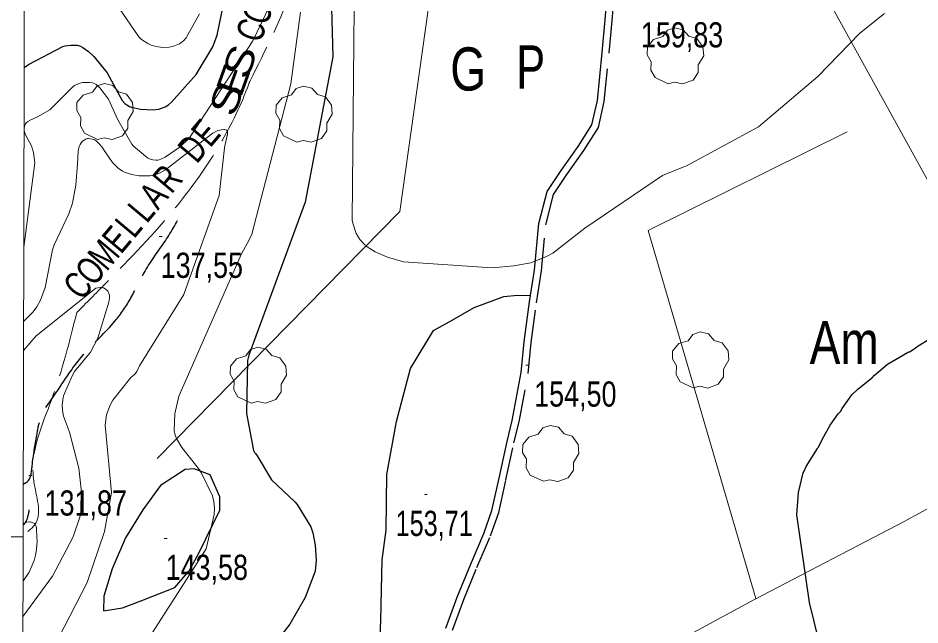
# Model space of a CAD drawing. Extents: x 483847 to 488453, y 4383581 to 4386795.
# Drawn here: x 484099.5 to 484413.1, y 4384469.3 to 4384680.3 of the extents above; entities that cross this region are included whole.
import ezdxf
from ezdxf.enums import TextEntityAlignment as Align

# ---------------------------------------------------------------- set-up
doc = ezdxf.new("R2010")
doc.units = 0
doc.header["$LTSCALE"] = 3.8
doc.linetypes.add('LONG_DASHED', pattern=[7.5, 6, -1.5])
doc.linetypes.add('MEDIUM_DASHED', pattern=[4.5, 3, -1.5])
for name, color, linetype, lineweight in [('1', 7, 'Continuous', 13), ('15', 7, 'LONG_DASHED', 13), ('25', 7, 'LONG_DASHED', 25), ('29', 7, 'Continuous', 13), ('38', 7, 'Continuous', 25), ('51', 7, 'Continuous', 13), ('7', 7, 'Continuous', 13), ('8', 7, 'Continuous', 25), ('9', 7, 'Continuous', 13)]:
    doc.layers.add(name, color=color, linetype=linetype, lineweight=lineweight)
doc.layers.add('31', color=7, linetype='Continuous')
doc.layers.add('5', color=7, linetype='Continuous')

msp = doc.modelspace()

# ---------------------------------------------------------------- linework, layer by layer
at = {"layer": '1'}
msp.add_line((484101.29, 4384500), (484031.19, 4384500), dxfattribs=at)
msp.add_lwpolyline([(484105.5, 4386448.1), (487681.9, 4386441.2), (487678, 4384129), (484100.5, 4384135.8)], close=True, dxfattribs=at)
at = {"layer": '15'}
for points in [[(484208.62, 4384780.98), (484204.46, 4384734.17), (484194.95, 4384691.19), (484180.05, 4384658.27)], [(484180.05, 4384658.27), (484179.75, 4384657.45), (484169.76, 4384636.54), (484154.56, 4384614.85), (484129.82, 4384587.96), (484119.88, 4384577.91)], [(484119.88, 4384577.91), (484111.2, 4384547.84), (484104.97, 4384519.31), (484105.58, 4384504.64), (484101.29, 4384500.6)]]:
    msp.add_spline(points, degree=3, dxfattribs=at)
at = {"layer": '25'}
msp.add_lwpolyline([(484247.62, 4384429.46), (484230.21, 4384421.96), (484225.82, 4384423.25), (484225.2, 4384427.09), (484224.83, 4384448.41), (484225.68, 4384470.98), (484226.15, 4384492), (484227.55, 4384502.3), (484227.75, 4384521.67), (484231.1, 4384540.04), (484235.95, 4384558.53), (484243.96, 4384571.74), (484250.5, 4384575.32), (484258.08, 4384579.74), (484268.39, 4384583.53), (484273.18, 4384583.98), (484277.7, 4384583.83)], dxfattribs=at)
msp.add_lwpolyline([(484162.32, 4384494.35), (484169.61, 4384509.2), (484169.64, 4384513.86), (484166.33, 4384521.56), (484160.73, 4384523.57), (484157.57, 4384523.34), (484149.04, 4384517.85), (484142.87, 4384509.33), (484136.8, 4384499.68), (484132.17, 4384488.8), (484129.27, 4384479.31), (484129.23, 4384474.25), (484135.76, 4384475.29), (484142.56, 4384477.86), (484154.01, 4384482.35), (484158.99, 4384488.17)], close=True, dxfattribs=at)
at = {"layer": '29'}
for points in [[(484325.53, 4384657.49), (484320.99, 4384659.61), (484319.58, 4384662.15), (484319.68, 4384665.13), (484318.31, 4384667.54), (484318.35, 4384670.29), (484320.51, 4384672.89), (484323.7, 4384673.89), (484325.35, 4384676.08), (484327.92, 4384676.91), (484330.78, 4384676.26), (484332.73, 4384673.99), (484335.54, 4384673.17), (484337.67, 4384670.32), (484337.91, 4384667.19), (484336.03, 4384664.04), (484336.03, 4384661.36), (484334.21, 4384658.75), (484330.59, 4384657.41), (484327.82, 4384658.04)], [(484127.16, 4384638.16), (484122.62, 4384640.28), (484121.21, 4384642.82), (484121.31, 4384645.8), (484119.94, 4384648.21), (484119.98, 4384650.96), (484122.14, 4384653.56), (484125.33, 4384654.56), (484126.98, 4384656.75), (484129.55, 4384657.58), (484132.41, 4384656.93), (484134.36, 4384654.66), (484137.17, 4384653.84), (484139.3, 4384650.99), (484139.54, 4384647.86), (484137.66, 4384644.71), (484137.66, 4384642.03), (484135.84, 4384639.42), (484132.22, 4384638.08), (484129.45, 4384638.71)], [(484196.38, 4384637.21), (484191.84, 4384639.33), (484190.43, 4384641.87), (484190.53, 4384644.85), (484189.16, 4384647.26), (484189.2, 4384650.01), (484191.36, 4384652.61), (484194.55, 4384653.61), (484196.2, 4384655.8), (484198.77, 4384656.63), (484201.63, 4384655.98), (484203.58, 4384653.71), (484206.39, 4384652.89), (484208.52, 4384650.04), (484208.76, 4384646.91), (484206.88, 4384643.76), (484206.88, 4384641.08), (484205.06, 4384638.47), (484201.44, 4384637.13), (484198.67, 4384637.76)], [(484334.3, 4384551.77), (484329.76, 4384553.89), (484328.35, 4384556.43), (484328.45, 4384559.41), (484327.08, 4384561.82), (484327.12, 4384564.57), (484329.28, 4384567.17), (484332.47, 4384568.17), (484334.12, 4384570.36), (484336.69, 4384571.19), (484339.55, 4384570.54), (484341.5, 4384568.27), (484344.31, 4384567.45), (484346.44, 4384564.6), (484346.68, 4384561.47), (484344.8, 4384558.32), (484344.8, 4384555.64), (484342.98, 4384553.03), (484339.36, 4384551.69), (484336.59, 4384552.32)], [(484180.5, 4384546.47), (484175.96, 4384548.59), (484174.55, 4384551.13), (484174.65, 4384554.11), (484173.28, 4384556.52), (484173.32, 4384559.27), (484175.48, 4384561.87), (484178.67, 4384562.87), (484180.32, 4384565.06), (484182.89, 4384565.89), (484185.75, 4384565.24), (484187.7, 4384562.97), (484190.51, 4384562.15), (484192.64, 4384559.3), (484192.88, 4384556.17), (484191, 4384553.02), (484191, 4384550.34), (484189.18, 4384547.73), (484185.56, 4384546.39), (484182.79, 4384547.02)], [(484282.16, 4384519.28), (484277.62, 4384521.4), (484276.21, 4384523.94), (484276.31, 4384526.92), (484274.94, 4384529.33), (484274.98, 4384532.08), (484277.14, 4384534.68), (484280.33, 4384535.68), (484281.98, 4384537.87), (484284.55, 4384538.7), (484287.41, 4384538.05), (484289.36, 4384535.78), (484292.17, 4384534.96), (484294.3, 4384532.11), (484294.54, 4384528.98), (484292.66, 4384525.83), (484292.66, 4384523.15), (484290.84, 4384520.54), (484287.22, 4384519.2), (484284.45, 4384519.83)]]:
    msp.add_lwpolyline(points, close=True, dxfattribs=at)
at = {"layer": '38'}
msp.add_lwpolyline([(484248.19, 4384468.22), (484252.22, 4384479.04), (484256.77, 4384490.25), (484261.45, 4384501.17), (484264.29, 4384509.12), (484266.77, 4384520.34), (484269.53, 4384533.14), (484271.3, 4384540.43), (484274.49, 4384557.09), (484275.44, 4384567.78), (484277.37, 4384581.71), (484279.08, 4384592.7), (484280.58, 4384608.85), (484283.45, 4384620.06), (484288.36, 4384627.3), (484294.23, 4384635.68), (484299.05, 4384643.25), (484300.94, 4384651.68), (484302.57, 4384668.39), (484303.7, 4384679.74), (484304.97, 4384695.22)], dxfattribs=at)
at = {"layer": '38', "linetype": 'MEDIUM_DASHED'}
msp.add_lwpolyline([(484250.55, 4384467.56), (484254.49, 4384478.15), (484259.02, 4384489.31), (484263.72, 4384500.28), (484266.65, 4384508.44), (484269.16, 4384519.82), (484271.91, 4384532.6), (484273.69, 4384539.91), (484276.92, 4384556.76), (484277.87, 4384567.5), (484279.78, 4384581.36), (484281.51, 4384592.4), (484282.99, 4384608.43), (484285.71, 4384619.04), (484290.37, 4384625.92), (484296.26, 4384634.32), (484301.34, 4384642.3), (484303.35, 4384651.29), (484305, 4384668.15), (484306.13, 4384679.52), (484306.87, 4384688.49)], dxfattribs=at)
at = {"layer": '38', "linetype": 'LONG_DASHED'}
for points in [[(484101.33, 4384518.38), (484102.3, 4384518.83), (484104.4, 4384524.68), (484106.01, 4384535.24), (484107.56, 4384541.84), (484111.62, 4384548.46), (484115.19, 4384553.78), (484122.27, 4384563.35), (484133.26, 4384575.06), (484138.74, 4384583.04), (484143.63, 4384592.36), (484150.73, 4384602.91), (484156.74, 4384613.15)], [(484103.24, 4384509.31), (484102.33, 4384505.56), (484101.3, 4384504)]]:
    msp.add_spline(points, degree=3, dxfattribs=at)
at = {"layer": '51'}
for points in [[(484278.96, 4384775.82), (484249.36, 4384756.77), (484242.13, 4384683.18), (484232.22, 4384613.05), (484147.85, 4384527.26)], [(484650.73, 4384748.47), (484664.63, 4384756.43), (484689.09, 4384713.56), (484566.87, 4384648.39), (484439.31, 4384581.4), (484372.98, 4384701.63)], [(484255.17, 4384427.24), (484292.82, 4384444.29), (484355.33, 4384478.1), (484407.83, 4384505.39), (484465.29, 4384536.85), (484507.21, 4384558.52), (484593.35, 4384604.73), (484673.49, 4384646.73), (484716.89, 4384670.38)], [(484356.1, 4384478.5), (484318.56, 4384606.52), (484387.79, 4384640.78)]]:
    msp.add_lwpolyline(points, dxfattribs=at)
at = {"layer": '7'}
for p, q in [((484148.58, 4384604.37), (484149.58, 4384604.37)), ((484276.12, 4384559.62), (484277.12, 4384559.62)), ((484103.29, 4384521.28), (484104.29, 4384521.28)), ((484240.79, 4384514.65), (484241.79, 4384514.65)), ((484150.32, 4384499.38), (484151.32, 4384499.38))]:
    msp.add_line(p, q, dxfattribs=at)
at = {"layer": '8'}
for points in [[(484101.64, 4384663.08), (484103.15, 4384664.15), (484115.04, 4384670.38), (484115.83, 4384670.62), (484117.86, 4384670.94), (484120.05, 4384670.92), (484121.2, 4384670.52), (484121.97, 4384670.13), (484123.93, 4384668.72), (484125.8, 4384667.01), (484130.48, 4384661.28), (484135.74, 4384651.71), (484136.62, 4384650.64), (484137.31, 4384650.14), (484138.26, 4384649.62), (484138.89, 4384649.4), (484142.06, 4384648.66), (484146.52, 4384648.46), (484148.42, 4384648.66), (484150.66, 4384649.51), (484151.75, 4384650.11), (484152.87, 4384651.13), (484161.44, 4384660.68), (484167.22, 4384670.27), (484168.71, 4384674.32), (484173.36, 4384696.92)], [(484208.22, 4384692.57), (484208.95, 4384666.8), (484199.29, 4384616.32), (484179.68, 4384563.16), (484179.28, 4384561.3), (484178.9, 4384542.87), (484181.35, 4384530), (484181.55, 4384529.5), (484181.71, 4384529.26), (484182.07, 4384528.9), (484182.69, 4384528.09)], [(484396.3, 4384555.1), (484396.47, 4384555.24), (484397.28, 4384556.16), (484401.82, 4384559.96), (484408.82, 4384564.08), (484409.29, 4384564.24), (484409.45, 4384564.32), (484411.16, 4384565.31), (484412.45, 4384566.35), (484416.32, 4384568.64)], [(484385.7, 4384432.3), (484374.66, 4384477.11), (484370.29, 4384507.59), (484370.92, 4384515.44), (484372.54, 4384522.2), (484372.73, 4384522.54), (484373.59, 4384524.41), (484377.46, 4384530.71), (484377.66, 4384530.91), (484377.73, 4384531.01), (484378.46, 4384532.29), (484379.08, 4384533.85), (484381.84, 4384538.8), (484384.68, 4384542.73), (484385.37, 4384543.39), (484385.5, 4384543.56), (484386.08, 4384544.6), (484389.47, 4384549.32), (484391.49, 4384551.31), (484396.3, 4384555.1)], [(484182.69, 4384528.09), (484187.59, 4384519.81), (484195.69, 4384512.19), (484196.49, 4384511.19), (484201.29, 4384503.4), (484202, 4384501.4), (484202.86, 4384497.1), (484203.19, 4384491.91), (484202.77, 4384488.02), (484199.35, 4384478.9), (484194.02, 4384469.65), (484191.54, 4384466.45), (484184.59, 4384460.76)]]:
    msp.add_lwpolyline(points, dxfattribs=at)
at = {"layer": '9'}
for p, q in [((484101.5, 4384600.55), (484101.51, 4384600.57)), ((484101.51, 4384600.61), (484101.51, 4384600.65)), ((484101.51, 4384600.57), (484101.51, 4384600.61))]:
    msp.add_line(p, q, dxfattribs=at)
for points in [[(484400.77, 4384681.88), (484392.24, 4384675.09), (484377.66, 4384660.04), (484356.99, 4384642.51), (484332.21, 4384629.06), (484323.62, 4384625.61), (484296.59, 4384607.25), (484285.46, 4384598.62), (484283.29, 4384597.4), (484277.76, 4384595.28), (484271.86, 4384594.13), (484264.31, 4384593.47), (484233.56, 4384595.61), (484227.92, 4384597.2), (484223.65, 4384599.08), (484220.9, 4384600.83), (484219.82, 4384601.66), (484218.46, 4384603.18), (484218.36, 4384603.37), (484218.26, 4384603.59), (484217.06, 4384605.46), (484215.88, 4384609.03), (484215.64, 4384610.04), (484216.85, 4384733.39)], [(484101.51, 4384600.65), (484105.27, 4384630.02), (484104.84, 4384633.54), (484104.14, 4384635.87), (484102.14, 4384639.47), (484101.75, 4384640.63), (484101.61, 4384641.51), (484101.62, 4384641.98), (484101.78, 4384642.79), (484102.11, 4384643.5), (484102.36, 4384643.85), (484102.93, 4384644.38), (484103.66, 4384644.84), (484106.22, 4384646.02), (484110.52, 4384648.45), (484118.64, 4384656.51), (484119.14, 4384656.85), (484120.17, 4384657.37), (484121.06, 4384657.7), (484121.84, 4384657.87), (484124.37, 4384657.94), (484125.29, 4384657.81), (484125.8, 4384657.63), (484126.69, 4384657.18), (484127.4, 4384656.6), (484127.88, 4384656.11), (484130.95, 4384652.07), (484134.17, 4384644.9), (484139.05, 4384636.47), (484139.68, 4384635.81), (484144.53, 4384631.74), (484145.02, 4384631.46), (484145.81, 4384631.14), (484146.37, 4384631), (484147.43, 4384630.92), (484148.15, 4384630.96), (484148.53, 4384631.03), (484149.18, 4384631.22), (484150.6, 4384631.94), (484155.88, 4384635.6), (484159.07, 4384638.71), (484181.11, 4384672.43), (484188.69, 4384688.11)], [(484162.64, 4384681.74), (484157.89, 4384673.4), (484157.11, 4384672.51), (484156.54, 4384672), (484155.63, 4384671.4), (484153.34, 4384670.46), (484152.01, 4384670.16), (484149.73, 4384670.13), (484147.55, 4384670.4), (484145.81, 4384670.9), (484144.58, 4384671.48), (484142.42, 4384672.9), (484141.46, 4384673.76), (484131.84, 4384687.95)], [(484197.73, 4384682.34), (484194.31, 4384657.43), (484180.78, 4384605.17), (484179.87, 4384603.24), (484177.23, 4384598.41), (484155.39, 4384548.91), (484154.04, 4384542.74), (484153.81, 4384536.98), (484154.07, 4384535.34), (484154.57, 4384534.16)], [(484101.45, 4384574.96), (484104.78, 4384578.25), (484106.07, 4384579.97), (484107.32, 4384582.21), (484108.9, 4384586.64), (484111.42, 4384599.7), (484112.03, 4384601.47), (484117.12, 4384612.32), (484118.44, 4384616.02), (484119.57, 4384622.27), (484120.14, 4384629.6), (484120.15, 4384629.63), (484120.41, 4384634.02), (484120.78, 4384635.66), (484121.07, 4384636.34), (484121.46, 4384636.94), (484121.95, 4384637.47), (484122.51, 4384637.91), (484123.11, 4384638.24), (484123.54, 4384638.4), (484123.74, 4384638.44), (484124.02, 4384638.44), (484125.21, 4384638.26), (484125.88, 4384638.09), (484126.22, 4384637.93), (484126.77, 4384637.52), (484127.74, 4384636.65), (484128.72, 4384635.39), (484129.71, 4384633.88), (484129.73, 4384633.86), (484129.75, 4384633.86), (484132.29, 4384630.16), (484134.27, 4384628.18), (484135.8, 4384627.12), (484136.5, 4384626.78), (484138.97, 4384625.96), (484141.57, 4384625.49), (484145.34, 4384625.43), (484146.96, 4384625.79), (484148.69, 4384626.42), (484150.78, 4384627.56), (484163.74, 4384637.63), (484163.75, 4384637.64), (484163.77, 4384637.65), (484167.27, 4384640.28), (484168.77, 4384641.06), (484170.15, 4384641.46), (484171.04, 4384641.58), (484171.24, 4384641.58), (484171.43, 4384641.56), (484171.93, 4384641.35), (484172.23, 4384641), (484172.28, 4384640.89), (484172.32, 4384640.77), (484172.34, 4384640.3), (484172.27, 4384639.63), (484172.25, 4384639.51)], [(484172.25, 4384639.51), (484171.26, 4384635.27), (484171.26, 4384635.25), (484171.26, 4384635.23), (484169.43, 4384618.61), (484157.41, 4384584.88), (484157.1, 4384584.22), (484141.74, 4384559.47), (484140.78, 4384557.47), (484140.21, 4384556.63), (484139.86, 4384556.25), (484138.75, 4384555.32), (484132.5, 4384547.54), (484131.38, 4384545.48), (484130.26, 4384542.36), (484129.72, 4384538.8), (484131.96, 4384515.35), (484129.58, 4384501.86), (484123.48, 4384484.09), (484111.6, 4384460.96), (484110.05, 4384458.73), (484101.18, 4384450.51)], [(484101.23, 4384472.37), (484111.48, 4384486.31), (484118.67, 4384499.99), (484120.92, 4384506.79), (484121.3, 4384508.71), (484121.47, 4384516.5), (484120.61, 4384523.89), (484117.37, 4384536.42), (484115.29, 4384541.94), (484115, 4384543.03), (484114.82, 4384545.64), (484115.01, 4384547.62), (484115.33, 4384549.01), (484118.29, 4384555.98), (484119.13, 4384557.41), (484124.68, 4384564.2), (484127.21, 4384568.99), (484131.06, 4384581.53), (484131.28, 4384583), (484131.25, 4384583.83), (484131.18, 4384584.23), (484130.99, 4384584.86), (484130.66, 4384585.4), (484130.41, 4384585.69), (484129.83, 4384586.16), (484129.17, 4384586.52), (484128.81, 4384586.63), (484128.17, 4384586.7), (484127.18, 4384586.56), (484126.53, 4384586.4), (484105.79, 4384569.83), (484101.43, 4384564.78)], [(484154.57, 4384534.16), (484156.46, 4384531.08), (484162.55, 4384523.24), (484163.23, 4384522.13), (484167.05, 4384514.25), (484167.57, 4384512.14), (484167.79, 4384509.96), (484167.69, 4384507.71), (484164.86, 4384495.81), (484132.55, 4384445.41), (484126.14, 4384438.95), (484112.18, 4384429.01), (484101.12, 4384424.02)], [(484101.25, 4384484.72), (484101.34, 4384484.81), (484103.3, 4384487.72), (484105.04, 4384491.71), (484105.04, 4384491.73), (484105.55, 4384493.6), (484105.87, 4384495.55), (484105.87, 4384495.57), (484106.09, 4384498.5), (484106.07, 4384499.88), (484106.07, 4384499.89), (484106.06, 4384499.92), (484105.9, 4384502.83), (484105.85, 4384503.14), (484105.61, 4384503.9), (484105.38, 4384504.35), (484105.28, 4384504.46), (484105.16, 4384504.56), (484104.64, 4384504.85), (484103.77, 4384505.19), (484103.63, 4384505.2), (484102.5, 4384505.06), (484102.41, 4384505.06), (484101.33, 4384504.64), (484101.3, 4384504.62)]]:
    msp.add_lwpolyline(points, dxfattribs=at)

# ---------------------------------------------------------------- texts
at = {"layer": '31'}
for s, width, p in [('G', 0.8, (484256.03, 4384655.12)), ('P', 0.75, (484277.76, 4384655.82)), ('Am', 0.8, (484386.78, 4384560.06))]:
    msp.add_text(s, height=15, dxfattribs=dict(at, width=width)).set_placement(p, align=Align.CENTER)
at = {"layer": '5'}
for s, rotation, width, p in [('O', 70.31, 0.75, (484187.22, 4384680.86)), ('C', 70.31, 0.75, (484184.96, 4384674.55)), ('S', 70.31, 1.3, (484181.06, 4384663.65)), ('E', 70.31, 1.2, (484178.73, 4384657.14)), ('S', 70.31, 1.3, (484176.41, 4384650.66)), ('E', 50.018, 0.75, (484168.35, 4384637.39)), ('D', 50.018, 0.75, (484163.85, 4384632.01)), ('R', 50.018, 0.75, (484155.05, 4384621.52)), ('A', 50.018, 0.75, (484150.18, 4384615.72)), ('L', 50.018, 0.75, (484145.94, 4384610.66)), ('L', 50.018, 0.75, (484141.5, 4384605.37)), ('E', 50.018, 0.75, (484137.33, 4384600.38)), ('M', 50.018, 0.75, (484132.84, 4384595.03)), ('O', 50.018, 0.75, (484128.22, 4384589.53)), ('C', 50.018, 0.75, (484123.91, 4384584.39))]:
    msp.add_text(s, height=9.49, rotation=rotation, dxfattribs=dict(at, width=width)).set_placement(p, align=Align.CENTER)
at = {"layer": '7'}
for s, width, p in [('159,83', 0.8, (484316.06, 4384670.12)), ('137,55', 0.8, (484149.08, 4384590)), ('154,50', 0.8, (484278.96, 4384545.25)), ('131,87', 0.8, (484108.7, 4384507.37)), ('153,71', 0.75, (484230.77, 4384500.28)), ('143,58', 0.8, (484150.82, 4384485.01))]:
    msp.add_text(s, height=8.75, dxfattribs=dict(at, width=width)).set_placement(p)

doc.saveas('drawing.dxf')
